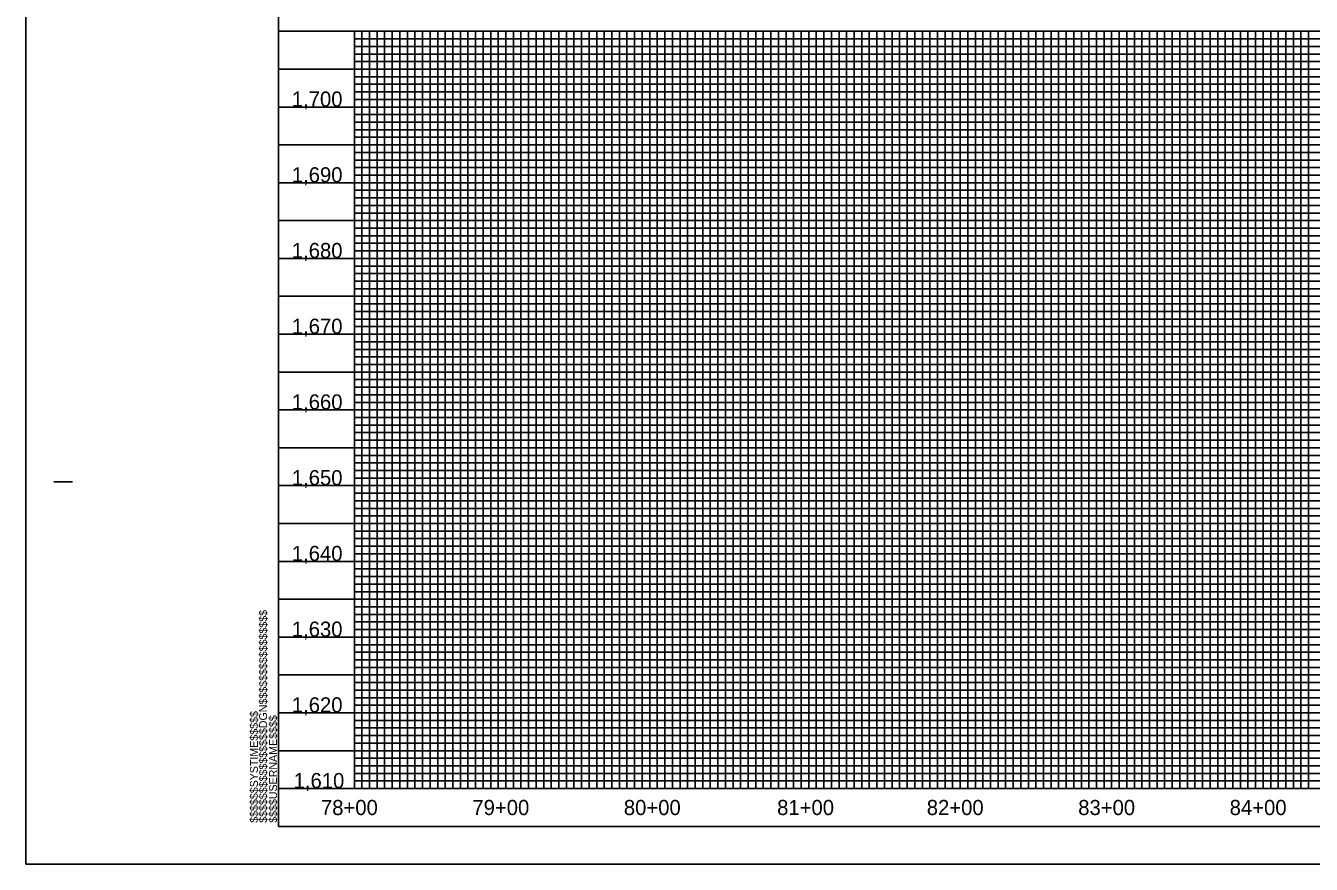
# Model space of a CAD drawing. Extents: x 505602 to 507286, y 483109 to 484209.
# Drawn here: x 505602 to 506451, y 483109 to 483662 of the extents above; entities that cross this region are included whole.
import ezdxf

# ---------------------------------------------------------------- set-up
doc = ezdxf.new("R2010")
doc.units = 0
for name, color, linetype in [('Exist Vertical Profile Vertical Axis Label', 7, 'Continuous'), ('Sheet Layout Profile Border Port 2', 7, 'Continuous'), ('Sheet Plot Border Outside CELL', 7, 'Continuous'), ('Sheet Profile CELL', 7, 'Continuous'), ('Sheet Profile Grid Major CELL', 7, 'Continuous'), ('Sheet Profile Grid Middle CELL', 7, 'Continuous'), ('Sheet Profile Grid Minor CELL', 7, 'Continuous')]:
    doc.layers.add(name, color=color, linetype=linetype)

msp = doc.modelspace()

# ---------------------------------------------------------------- linework, layer by layer
at = {"layer": 'Sheet Layout Profile Border Port 2'}
msp.add_lwpolyline([(505819.08, 483658.71), (507219.08, 483658.71), (507219.08, 483158.71), (505819.08, 483158.71)], close=True, dxfattribs=at)
at = {"layer": 'Sheet Plot Border Outside CELL'}
msp.add_lwpolyline([(505602.08, 483108.71), (507286.08, 483108.71), (507286.08, 484208.71), (505602.08, 484208.71)], close=True, dxfattribs=at)
at = {"layer": 'Sheet Profile CELL'}
for p, q in [((505769.08, 483658.71), (507269.08, 483658.71)), ((505620.58, 483361.21), (505633.08, 483361.21)), ((507269.08, 483158.71), (505769.08, 483158.71)), ((505769.08, 483133.71), (507269.08, 483133.71)), ((505769.08, 483133.71), (505769.08, 483133.71)), ((505769.08, 483133.71), (505769.08, 483133.71)), ((505769.08, 483133.71), (505769.08, 483133.71)), ((505769.08, 483133.71), (505769.08, 483133.71)), ((505769.08, 483133.71), (505769.08, 483133.71)), ((505769.08, 483133.71), (505769.08, 483133.71)), ((505769.08, 483133.71), (505769.08, 483133.71))]:
    msp.add_line(p, q, dxfattribs=at)
msp.add_lwpolyline([(507269.08, 484183.71), (505769.08, 484183.71), (505769.08, 483133.71), (507269.08, 483133.71)], close=True, dxfattribs=at)
msp.add_lwpolyline([(505806.58, 483133.71), (505806.58, 483133.71)], dxfattribs=at)
at = {"layer": 'Sheet Profile Grid Major CELL'}
for p, q in [((506269.08, 483658.71), (506319.08, 483658.71)), ((506369.08, 483658.71), (506419.08, 483658.71))]:
    msp.add_line(p, q, dxfattribs=at)
for points in [[(505819.08, 483658.71), (505819.08, 483158.71), (505869.08, 483158.71), (505869.08, 483658.71), (505919.08, 483658.71), (505919.08, 483158.71), (505969.08, 483158.71), (505969.08, 483658.71), (506019.08, 483658.71), (506019.08, 483158.71), (506069.08, 483158.71), (506069.08, 483658.71), (506119.08, 483658.71), (506119.08, 483158.71), (506169.08, 483158.71), (506169.08, 483658.71), (506219.08, 483658.71), (506219.08, 483158.71), (506269.08, 483158.71), (506269.08, 483658.71), (506319.08, 483658.71), (506319.08, 483158.71), (506369.08, 483158.71), (506369.08, 483658.71), (506419.08, 483658.71), (506419.08, 483158.71), (506469.08, 483158.71)], [(507269.08, 483608.71), (505769.08, 483608.71)], [(507269.08, 483558.71), (505769.08, 483558.71), (505769.08, 483508.71), (507269.08, 483508.71)], [(507269.08, 483458.71), (505769.08, 483458.71), (505769.08, 483408.71), (507269.08, 483408.71)], [(507269.08, 483358.71), (505769.08, 483358.71), (505769.08, 483308.71), (507269.08, 483308.71)], [(507269.08, 483258.71), (505769.08, 483258.71), (505769.08, 483258.71), (505769.08, 483208.71), (507269.08, 483208.71)], [(507269.08, 483158.71), (505769.08, 483158.71)]]:
    msp.add_lwpolyline(points, dxfattribs=at)
at = {"layer": 'Sheet Profile Grid Middle CELL'}
for points in [[(505794.08, 483658.71), (505844.08, 483658.71), (505844.08, 483158.71), (505894.08, 483158.71), (505894.08, 483658.71), (505944.08, 483658.71), (505944.08, 483158.71), (505994.08, 483158.71), (505994.08, 483658.71), (506044.08, 483658.71), (506044.08, 483158.71), (506094.08, 483158.71), (506094.08, 483658.71), (506144.08, 483658.71), (506144.08, 483158.71), (506194.08, 483158.71), (506194.08, 483658.71), (506244.08, 483658.71), (506244.08, 483158.71), (506294.08, 483158.71), (506294.08, 483658.71), (506344.08, 483658.71), (506344.08, 483158.71), (506394.08, 483158.71), (506394.08, 483158.71), (506394.08, 483658.71), (506444.08, 483658.71), (506444.08, 483158.71), (506494.08, 483158.71)], [(505769.08, 483633.71), (507269.08, 483633.71)], [(507269.08, 483583.71), (505769.08, 483583.71), (505769.08, 483533.71), (507269.08, 483533.71)], [(507269.08, 483483.71), (505769.08, 483483.71), (505769.08, 483433.71), (507269.08, 483433.71)], [(507269.08, 483383.71), (505769.08, 483383.71), (505769.08, 483333.71), (507269.08, 483333.71)], [(507269.08, 483283.71), (505769.08, 483283.71), (505769.08, 483233.71), (507269.08, 483233.71)], [(507269.08, 483183.71), (505769.08, 483183.71)]]:
    msp.add_lwpolyline(points, dxfattribs=at)
at = {"layer": 'Sheet Profile Grid Minor CELL'}
for p, q in [((505819.08, 483653.71), (507219.08, 483653.71)), ((507219.08, 483648.71), (505819.08, 483648.71)), ((505819.08, 483643.71), (507219.08, 483643.71)), ((507219.08, 483638.71), (505819.08, 483638.71)), ((505819.08, 483628.71), (507219.08, 483628.71)), ((507219.08, 483623.71), (505819.08, 483623.71)), ((505819.08, 483618.71), (507219.08, 483618.71)), ((507219.08, 483613.71), (505819.08, 483613.71)), ((505819.08, 483603.71), (507219.08, 483603.71)), ((507219.08, 483598.71), (505819.08, 483598.71)), ((505819.08, 483593.71), (507219.08, 483593.71)), ((507219.08, 483588.71), (505819.08, 483588.71)), ((505819.08, 483578.71), (507219.08, 483578.71)), ((507219.08, 483573.71), (505819.08, 483573.71)), ((505819.08, 483568.71), (507219.08, 483568.71)), ((507219.08, 483563.71), (505819.08, 483563.71)), ((505819.08, 483553.71), (507219.08, 483553.71)), ((507219.08, 483548.71), (505819.08, 483548.71)), ((505819.08, 483543.71), (507219.08, 483543.71)), ((507219.08, 483538.71), (505819.08, 483538.71)), ((505819.08, 483528.71), (507219.08, 483528.71)), ((507219.08, 483523.71), (505819.08, 483523.71)), ((505819.08, 483518.71), (507219.08, 483518.71)), ((507219.08, 483513.71), (505819.08, 483513.71)), ((505819.08, 483503.71), (507219.08, 483503.71)), ((507219.08, 483498.71), (505819.08, 483498.71)), ((505819.08, 483493.71), (507219.08, 483493.71)), ((507219.08, 483488.71), (505819.08, 483488.71)), ((505819.08, 483478.71), (507219.08, 483478.71)), ((507219.08, 483473.71), (505819.08, 483473.71)), ((505819.08, 483468.71), (507219.08, 483468.71)), ((507219.08, 483463.71), (505819.08, 483463.86)), ((505819.08, 483453.71), (507219.08, 483453.71)), ((507219.08, 483448.71), (505819.08, 483448.71)), ((505819.08, 483443.71), (507219.08, 483443.71)), ((507219.08, 483438.71), (505819.08, 483438.71)), ((505819.08, 483428.71), (507219.08, 483428.71)), ((507219.08, 483423.71), (505819.08, 483423.71)), ((505819.08, 483418.71), (507219.08, 483418.71)), ((507219.08, 483413.71), (505819.08, 483413.71)), ((505819.08, 483403.71), (507219.08, 483403.71)), ((507219.08, 483398.71), (505819.08, 483398.71)), ((505819.08, 483393.71), (507219.08, 483393.71)), ((507219.08, 483388.71), (505819.08, 483388.71)), ((505819.08, 483378.71), (507219.08, 483378.71)), ((507219.08, 483373.71), (505819.08, 483373.71)), ((505819.08, 483368.71), (507219.08, 483368.71)), ((507219.08, 483363.71), (505819.08, 483363.71)), ((505819.08, 483353.71), (507219.08, 483353.71)), ((507219.08, 483348.71), (505819.08, 483348.71)), ((505819.08, 483343.71), (507219.08, 483343.71)), ((507219.08, 483338.71), (505819.08, 483338.71)), ((505819.08, 483328.71), (507219.08, 483328.71)), ((507219.08, 483323.71), (505819.08, 483323.71)), ((505819.08, 483318.71), (507219.08, 483318.71)), ((507219.08, 483313.71), (505819.08, 483313.71)), ((505819.08, 483303.71), (507219.08, 483303.71)), ((507219.08, 483298.71), (505819.08, 483298.71)), ((505819.08, 483293.71), (507219.08, 483293.71)), ((507219.08, 483288.71), (505819.08, 483288.71)), ((505819.08, 483278.71), (507219.08, 483278.71)), ((507219.08, 483273.71), (505819.08, 483273.71)), ((505819.08, 483268.71), (507219.08, 483268.71)), ((507219.08, 483263.71), (505819.08, 483263.71)), ((505819.08, 483253.71), (507219.08, 483253.71)), ((507219.08, 483248.71), (505819.08, 483248.71)), ((505819.08, 483243.71), (507219.08, 483243.71)), ((507219.08, 483238.71), (505819.08, 483238.71)), ((505819.08, 483228.71), (507219.08, 483228.71)), ((507219.08, 483223.71), (505819.08, 483223.71)), ((505819.08, 483218.71), (507219.08, 483218.71)), ((507219.08, 483213.71), (505819.08, 483213.71)), ((505819.08, 483203.71), (507219.08, 483203.71)), ((507219.08, 483198.71), (505819.08, 483198.71)), ((505819.08, 483193.71), (507219.08, 483193.71)), ((507219.08, 483188.71), (505819.08, 483188.71)), ((505819.08, 483178.71), (507219.08, 483178.71)), ((507219.08, 483173.71), (505819.08, 483173.71)), ((505819.08, 483168.71), (507219.08, 483168.71)), ((505819.08, 483163.71), (507219.08, 483163.71))]:
    msp.add_line(p, q, dxfattribs=at)
for points in [[(505819.08, 483658.71), (505824.08, 483658.71), (505824.08, 483158.71), (505829.08, 483158.71), (505829.08, 483658.71), (505834.08, 483658.71), (505834.08, 483158.71), (505839.08, 483158.71), (505839.08, 483658.71), (505849.08, 483658.71), (505849.08, 483158.71), (505854.08, 483158.71), (505854.08, 483658.71), (505859.08, 483658.71), (505859.08, 483158.71), (505864.08, 483158.71), (505874.08, 483158.71), (505879.08, 483158.71), (505879.08, 483658.71), (505884.08, 483658.71), (505884.08, 483158.71), (505889.08, 483158.71), (505889.08, 483658.71), (505899.08, 483658.71), (505899.08, 483158.71), (505904.08, 483158.71), (505904.08, 483658.71), (505909.08, 483658.71), (505909.08, 483158.71), (505914.08, 483158.71), (505914.08, 483658.71), (505924.08, 483658.71), (505924.08, 483158.71), (505929.08, 483158.71), (505929.08, 483658.71), (505934.08, 483658.71), (505934.08, 483158.71), (505939.08, 483158.71), (505939.08, 483658.71), (505949.08, 483658.71), (505949.08, 483158.71), (505954.08, 483158.71), (505954.08, 483658.71), (505959.08, 483658.71), (505959.08, 483158.71), (505964.08, 483158.71), (505964.08, 483658.71), (505974.08, 483658.71), (505974.08, 483158.71), (505979.08, 483158.71), (505979.08, 483658.71), (505984.08, 483658.71), (505984.08, 483158.71), (505989.08, 483158.71), (505989.08, 483658.71), (505999.08, 483658.71), (505999.08, 483158.71), (506004.08, 483158.71), (506004.08, 483658.71), (506009.08, 483658.71), (506009.08, 483158.71), (506014.08, 483158.71), (506014.08, 483658.71), (506024.08, 483658.71), (506024.08, 483158.71), (506029.08, 483158.71), (506029.08, 483658.71), (506034.08, 483658.71), (506034.08, 483158.71)], [(505864.08, 483158.71), (505864.08, 483658.71), (505874.08, 483658.71), (505874.08, 483158.71)], [(506034.08, 483158.71), (506039.08, 483158.71), (506039.08, 483658.71), (506049.08, 483658.71), (506049.08, 483158.71), (506054.08, 483158.71), (506054.08, 483658.71), (506059.08, 483658.71), (506059.08, 483158.71), (506064.08, 483158.71), (506064.08, 483658.71), (506074.08, 483658.71), (506074.08, 483158.71), (506079.08, 483158.71), (506079.08, 483658.71), (506084.08, 483658.71), (506084.08, 483158.71), (506089.08, 483158.71), (506089.08, 483658.71), (506099.08, 483658.71), (506099.08, 483158.71), (506104.08, 483158.71), (506104.08, 483658.71), (506109.08, 483658.71), (506109.08, 483158.71), (506114.08, 483158.71), (506114.08, 483658.71), (506124.08, 483658.71), (506124.08, 483158.71), (506129.08, 483158.71), (506129.08, 483658.71), (506134.08, 483658.71), (506134.08, 483158.71), (506139.08, 483158.71), (506139.08, 483658.71), (506149.08, 483658.71), (506149.08, 483158.71), (506154.08, 483158.71), (506154.08, 483658.71), (506159.08, 483658.71), (506159.08, 483158.71), (506164.08, 483158.71), (506164.08, 483658.71), (506174.08, 483658.71), (506174.08, 483158.71), (506179.08, 483158.71), (506179.08, 483658.71), (506184.08, 483658.71), (506184.08, 483158.71), (506189.08, 483158.71), (506189.08, 483658.71), (506199.08, 483658.71), (506199.08, 483158.71), (506204.08, 483158.71), (506204.08, 483658.71), (506209.08, 483658.71), (506209.08, 483158.71), (506214.08, 483158.71), (506214.08, 483658.71), (506224.08, 483658.71), (506224.08, 483158.71), (506229.08, 483158.71), (506229.08, 483658.71), (506234.08, 483658.71), (506234.08, 483158.71), (506239.08, 483158.71), (506239.08, 483658.71), (506249.08, 483658.71), (506249.08, 483158.71), (506254.08, 483158.71), (506254.08, 483658.71), (506259.08, 483658.71), (506259.08, 483158.71), (506264.08, 483158.71), (506264.08, 483658.71), (506274.08, 483658.71), (506274.08, 483158.71), (506279.08, 483158.71), (506279.08, 483658.71), (506284.08, 483658.71), (506284.08, 483158.71), (506289.08, 483158.71), (506289.08, 483658.71), (506299.08, 483658.71), (506299.08, 483158.71), (506304.08, 483158.71), (506304.08, 483658.71), (506309.08, 483658.71), (506309.08, 483158.71), (506314.08, 483158.71), (506314.08, 483658.71), (506324.08, 483658.71), (506324.08, 483158.71), (506329.08, 483158.71), (506329.08, 483658.71), (506334.08, 483658.71), (506334.08, 483158.71), (506339.08, 483158.71), (506339.08, 483658.71), (506349.08, 483658.71)], [(506349.08, 483658.71), (506349.08, 483158.71), (506354.08, 483158.71), (506354.08, 483658.71), (506359.08, 483658.71), (506359.08, 483158.71), (506364.08, 483158.71), (506364.08, 483658.71), (506374.08, 483658.71), (506374.08, 483158.71), (506379.08, 483158.71), (506379.08, 483658.71), (506384.08, 483658.71), (506384.08, 483158.71), (506389.08, 483158.71), (506389.08, 483658.71), (506399.08, 483658.71), (506399.08, 483158.71), (506404.08, 483158.71), (506404.08, 483658.71), (506409.08, 483658.71), (506409.08, 483158.71), (506414.08, 483158.71), (506414.08, 483658.71), (506424.08, 483658.71), (506424.08, 483158.71), (506429.08, 483158.71), (506429.08, 483658.71), (506434.08, 483658.71), (506434.08, 483158.71), (506439.08, 483158.71), (506439.08, 483658.71), (506449.08, 483658.71), (506449.08, 483158.71), (506454.08, 483158.71)]]:
    msp.add_lwpolyline(points, dxfattribs=at)

# ---------------------------------------------------------------- texts
at = {"layer": 'Exist Vertical Profile Vertical Axis Label'}
for s, p in [('1,700', (505777.78, 483608.96)), ('1,690', (505777.78, 483558.96)), ('1,680', (505777.78, 483508.96)), ('1,670', (505777.78, 483458.96)), ('1,660', (505777.78, 483408.96)), ('1,650', (505777.78, 483358.96)), ('1,640', (505777.78, 483308.96)), ('1,630', (505777.78, 483258.96)), ('1,620', (505777.78, 483208.96)), ('1,610', (505778.97, 483158.96)), ('78+00', (505797.01, 483141.21)), ('79+00', (505897.01, 483141.21)), ('80+00', (505997.01, 483141.21)), ('81+00', (506098.21, 483141.21)), ('82+00', (506197.01, 483141.21)), ('83+00', (506297.01, 483141.21)), ('84+00', (506397.01, 483141.21))]:
    msp.add_text(s, height=10, dxfattribs=at).set_placement(p)
at = {"layer": 'Sheet Profile CELL'}
for s, p in [('$$$$$$$$$$$$$$$$DGN$$$$$$$$$$$$$$$$', (505761.44, 483136.09)), ('$$$$$$SYSTIME$$$$$', (505755.39, 483136.09)), ('$$$$USERNAME$$$$', (505768.02, 483136.1))]:
    msp.add_text(s, height=5.25, rotation=90, dxfattribs=at).set_placement(p)

doc.saveas('drawing.dxf')
